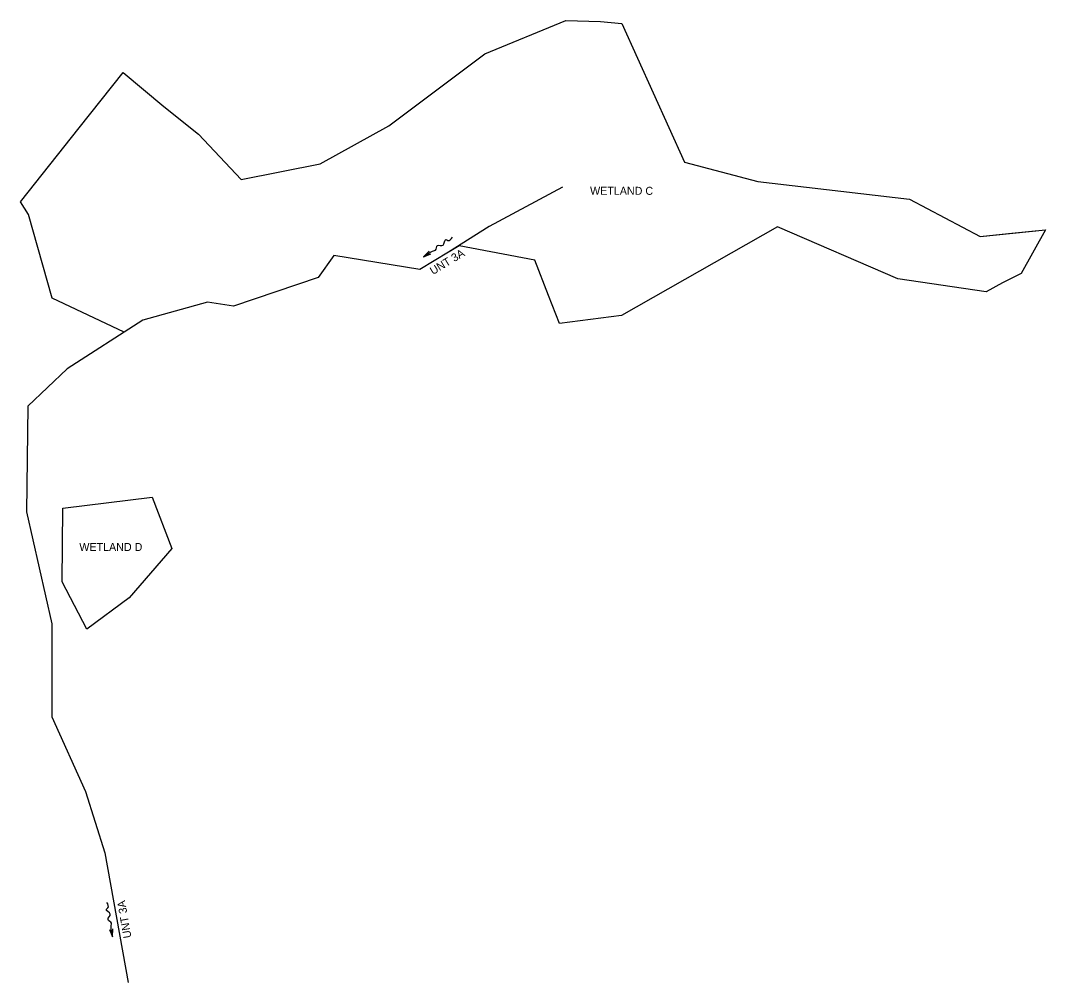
# Model space of a CAD drawing. Extents: x 144323 to 145863, y 512481 to 514373.
# Drawn here: x 144744.2 to 145102.9, y 513292 to 513628.7 of the extents above; entities that cross this region are included whole.
import ezdxf

# ---------------------------------------------------------------- set-up
doc = ezdxf.new("R2010")
doc.units = 0
for name, color, linetype in [('HY_X_Text', 7, 'Continuous'), ('HY_X_Water_Edge', 7, 'Continuous'), ('HY_X_Wetland_Area', 7, 'Continuous')]:
    doc.layers.add(name, color=color, linetype=linetype)

msp = doc.modelspace()

# ---------------------------------------------------------------- linework, layer by layer
at = {"layer": 'HY_X_Text'}
for p, q in [((144887.23, 513547.97), (144885.23, 513545.93)), ((144885.23, 513545.93), (144887.86, 513547.04)), ((144775.44, 513310.6), (144776.44, 513307.93)), ((144776.44, 513307.93), (144776.55, 513310.78))]:
    msp.add_line(p, q, dxfattribs=at)
for points in [[(144894.03, 513547.56), (144884.02, 513541.49), (144853.83, 513546.37), (144848.35, 513538.72), (144818.74, 513528.66), (144809.69, 513530.06), (144787.02, 513523.74), (144780.55, 513519.59), (144755.35, 513531.55), (144747.1, 513560.81), (144744.24, 513565.19), (144764.72, 513591.05), (144780.12, 513610.5), (144794.45, 513598.56), (144806.47, 513588.85), (144821.41, 513573.06), (144849.08, 513578.51), (144873.17, 513591.8), (144906.77, 513616.98), (144935.02, 513628.67), (144947.19, 513628.29), (144954.61, 513627.67), (144976.59, 513579.04), (145002.24, 513572.32), (145055.29, 513566.13), (145080.02, 513553.12), (145102.89, 513555.42), (145094.32, 513540.18), (145087.87, 513536.88), (145082.1, 513533.75), (145051.24, 513538.3), (145009.08, 513556.41), (144954.51, 513525.42), (144932.83, 513522.59), (144929, 513532.44), (144924.19, 513544.81), (144897.68, 513549.77), (144894.2, 513547.67)], [(144759.11, 513457.98), (144790.37, 513461.88), (144797.16, 513443.9), (144782.22, 513426.6), (144767.47, 513415.62), (144758.8, 513432.25)]]:
    msp.add_lwpolyline(points, close=True, dxfattribs=at)
for points in [[(144885.23, 513545.93), (144887.63, 513547.56), (144888.7, 513548.05), (144889.41, 513548.3), (144890.09, 513549.93), (144892.1, 513549.99), (144893.12, 513551.99), (144893.77, 513551.73), (144895.36, 513552.82)], [(144776.44, 513307.93), (144775.98, 513310.8), (144775.99, 513311.97), (144776.06, 513312.72), (144774.88, 513314.03), (144775.67, 513315.88), (144774.3, 513317.64), (144774.81, 513318.13), (144774.49, 513320.02)]]:
    msp.add_spline(points, degree=3, dxfattribs=at)
at = {"layer": 'HY_X_Water_Edge'}
msp.add_lwpolyline([(144933.85, 513570.36), (144908.24, 513556.6), (144894.03, 513547.56), (144884.02, 513541.49), (144853.83, 513546.37), (144848.35, 513538.72), (144818.74, 513528.66), (144809.69, 513530.06), (144787.02, 513523.74), (144760.54, 513506.75), (144746.81, 513493.65), (144746.39, 513456.72), (144755.19, 513417.48), (144755.16, 513385.01), (144766.99, 513358.79), (144773.81, 513337.39), (144781.88, 513292)], dxfattribs=at)
at = {"layer": 'HY_X_Wetland_Area'}
for points in [[(144794.45, 513598.56), (144806.47, 513588.85), (144821.41, 513573.06), (144849.08, 513578.51), (144873.17, 513591.8), (144906.77, 513616.98), (144935.02, 513628.67), (144947.19, 513628.29), (144954.61, 513627.67), (144976.59, 513579.04), (145002.24, 513572.32), (145055.29, 513566.13), (145080.02, 513553.12), (145089.89, 513554.12), (145096.99, 513554.83), (145102.89, 513555.42), (145094.32, 513540.18), (145087.87, 513536.88), (145082.1, 513533.75), (145051.24, 513538.3), (145009.08, 513556.41), (144954.51, 513525.42), (144932.83, 513522.59), (144929, 513532.44), (144924.19, 513544.81), (144897.68, 513549.77), (144894.2, 513547.67), (144894.03, 513547.56), (144884.02, 513541.49), (144853.83, 513546.37), (144848.35, 513538.72), (144818.74, 513528.66), (144809.69, 513530.06), (144787.02, 513523.74), (144780.55, 513519.59), (144755.35, 513531.55), (144747.1, 513560.81), (144744.24, 513565.19), (144764.72, 513591.05), (144780.12, 513610.5)], [(144759.11, 513457.98), (144790.37, 513461.88), (144797.16, 513443.9), (144782.22, 513426.6), (144767.47, 513415.62), (144758.8, 513432.25)]]:
    msp.add_lwpolyline(points, close=True, dxfattribs=at)

# ---------------------------------------------------------------- texts
at = {"layer": 'HY_X_Text'}
for s, p in [('WETLAND C', (144943.54, 513567.66)), ('WETLAND D', (144764.83, 513443.01))]:
    msp.add_text(s, height=2.8, dxfattribs=at).set_placement(p)
for rotation, p in [(31.3253, (144888.56, 513539.55)), (99.8051, (144783.08, 513307.76))]:
    msp.add_text('UNT 3A', height=2.8, rotation=rotation, dxfattribs=at).set_placement(p)

doc.saveas('drawing.dxf')
